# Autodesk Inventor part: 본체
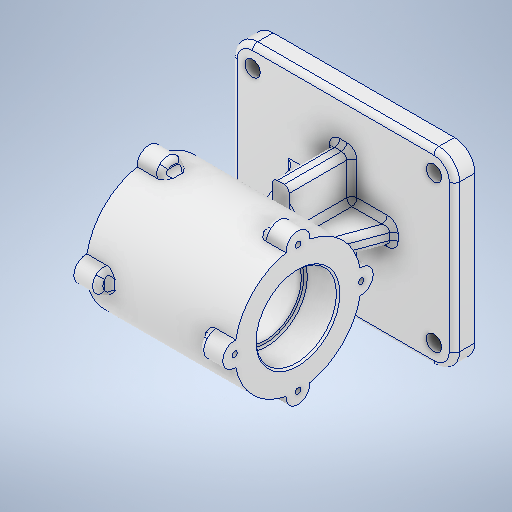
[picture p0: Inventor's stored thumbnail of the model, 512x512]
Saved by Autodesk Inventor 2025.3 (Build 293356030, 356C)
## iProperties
Created: 2025-08
Part Number: 본체
Material: 알루미늄 6061
Document SubType Name: Modeling
Designer: infra011
Density: 2.7 g/cm^3
Appearance: 알루미늄 - 평지
Mass: 1211.2 g
Surface Area: 801.125 cm^2
Volume: 448.594 cm^3
Author: infra011
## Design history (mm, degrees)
sketch "스케치1"
  geometry: L1 (-65, 55)-(65, 55); L2 (65, 55)-(65, -55); L3 (65, -55)-(-65, -55); L4 (-65, -55)-(-65, 55); L5 (-65, 55)-(65, -55); L6 (65, 55)-(-65, -55); 1 further point
  constraints: 12 end point, 2 midpoint, 2 parallel, 1 horizontal, 1 perpendicular
  dimensions: "d0" = 130 distance of L2.end L3.end; "d1" = 110 distance of L1.end L2.end
extrude "돌출1" new body sketch "스케치1" distance "d2" = 12; taper "d3" = 0 deg
sketch "스케치2"
  geometry: L1 (-53, 43)-(53, 43); L2 (53, 43)-(53, -43); L3 (53, -43)-(-53, -43); L4 (-53, -43)-(-53, 43); L5 (-53, 43)-(53, -43); L6 (53, 43)-(-53, -43); 1 further point
  constraints: 12 end point, 2 midpoint, 2 parallel, 1 horizontal, 1 perpendicular
  dimensions: "d4" = 106 distance of L2.end L3.end; "d5" = 86 distance of L1.end L2.end
hole "구멍1" sketch "스케치2" at (-53, 43), (53, -43), (53, 43), (-53, -43) diameter "d6" = 9; stored, may be unused: countersink angle "d10" = 90 deg, drill point angle "d12" = 0 deg; dims "d7" = 8, "d8" = 4, "d9" = 2, "d11" = 12
sketch "스케치3"
  geometry: L1 (43.5, 119)-(-43.5, 119); L2 (-43.5, 119)-(-43.5, 82); L3 (-43.5, 82)-(43.5, 82); L4 (43.5, 82)-(43.5, 119); L5 (43.5, 119)-(-43.5, 82); L6 (-43.5, 119)-(43.5, 82); L7 (65, 0)-(-65, 0) reference; 5 further points
  constraints: 12 end point, 5 midpoint, 2 parallel, 1 horizontal, 1 perpendicular, 1 vertical alignment
  dimensions: "d14" = 37 distance of L1.end L2.end; "d15" = 87 distance of L1.start L1.end; "d16" = 82 distance of point (0, 0) point (0, 82)
revolve "회전1" sketch "스케치3" stored, may be unused: angle "d17" = 90 deg
sketch "스케치4"
  geometry: L1 (43.5, 45)-(43.5, 119) reference; L2 (43.5, 105.5)-(24.5, 105.5); L3 (24.5, 105.5)-(24.5, 82); L4 (24.5, 82)-(43.5, 82); L5 (43.5, 82)-(43.5, 105.5); L6 (24.5, 103)-(-24.5, 103); L7 (-24.5, 103)-(-24.5, 82); L8 (-24.5, 82)-(24.5, 82); L9 (24.5, 82)-(24.5, 103); L10 (-24.5, 105.5)-(-43.5, 105.5); L11 (-43.5, 105.5)-(-43.5, 82); L12 (-43.5, 82)-(-24.5, 82); L13 (-24.5, 82)-(-24.5, 105.5); L14 (-43.5, 45)-(-43.5, 119) reference; L15 (43.5, 45)-(43.5, 119) reference; L16 (-43.5, 45)-(43.5, 45) reference; 4 further points
  constraints: 24 end point, 6 parallel, 3 horizontal, 3 perpendicular, 2 collinear, 2 point on line
  dimensions: "d18" = 19 distance between parallel lines of L5 L9; "d19" = 19 distance between parallel lines of L14 L7; "d20" = 21 distance between parallel lines of L8 L6; "d21" = 23.5 distance between parallel lines of L4 L2; "d22" = 23.5 distance between parallel lines of L12 L10; "d23" = 37 distance between parallel lines of L16 L4; "d24" = 37 distance between parallel lines of L16 L12
revolve "회전2" sketch "스케치4" stored, may be unused: angle "d25" = 90 deg
sketch "스케치5"
  geometry: L1 (0, 0)-(37, 0); C1 r 23.5 at (0, 0) reference; C2 r 7 at (37, 0); C3 r 7 at (0, 37); C4 r 7 at (-37, 0); C5 r 7 at (0, -37); 13 further points
  constraints: 5 coincident, 4 centre point, 2 end point, 1 horizontal, 15 other
  dimensions: "d26" = 14 diameter of C2; "d29" = 360 deg dimension on C1.centre C2.centre (derived)
extrude "돌출2" join sketch "스케치5" distance "d31" = 14; taper "d32" = 0 deg
sketch "스케치6"
  geometry: C1 r 23.5 at (0, 0) reference; C2 r 37 at (0, 0) reference; C3 r 7 at (-37, 0); C4 r 7 at (0, 37); C5 r 7 at (37, 0); C6 r 7 at (0, -37); A1 r 37 centre (0, 0) between (-36.338, 6.969) and (-36.338, -6.969) reference; A2 r 7 centre (-37, 0) between (-36.338, 6.969) and (-36.338, -6.969) reference; A3 r 37 centre (0, 0) between (6.969, 36.338) and (-6.969, 36.338) reference; A4 r 7 centre (0, 37) between (6.969, 36.338) and (-6.969, 36.338) reference; A5 r 37 centre (0, 0) between (36.338, -6.969) and (36.338, 6.969) reference; A6 r 7 centre (37, 0) between (36.338, -6.969) and (36.338, 6.969) reference; A7 r 37 centre (0, 0) between (-6.969, -36.338) and (6.969, -36.338) reference; A8 r 7 centre (0, -37) between (-6.969, -36.338) and (6.969, -36.338) reference; 8 further points
  constraints: 4 centre point, 4 coincident, 1 point on circle
  dimensions: "d33" = 14 diameter of C6; "d34" = 14 diameter of C4; "d35" = 14 diameter of C3; "d36" = 14 diameter of C5
extrude "돌출3" join sketch "스케치6" distance "d37" = 14; taper "d38" = 0 deg
fillet "모깎기1" dims "d39" = 1
chamfer "모따기1" distance "d40" = 1; stored, may be unused: second distance "d41" = 2, angle "d42" = 45 deg
chamfer "모따기2" distance "d43" = 1; stored, may be unused: second distance "d44" = 2, angle "d45" = 45 deg
sketch "스케치7"
  geometry: L1 (43.5, 88.969)-(29.5, 88.969) reference; L2 (29.5, 88.969)-(29.5, 75.031) reference; L3 (29.5, 75.031)-(43.5, 75.031) reference; L4 (43.5, 45.662)-(43.5, 75.031) reference; L5 (43.5, 45.662)-(29.5, 45.662) reference; L6 (29.5, 45.662)-(29.5, 45.662) reference; L7 (29.5, 45.662)-(43.5, 45.662) reference; L8 (43.5, 75.031)-(43.5, 45.662) reference; L9 (43.5, 75.031)-(29.5, 75.031) reference; L10 (29.5, 75.031)-(29.5, 88.969) reference; L11 (29.5, 88.969)-(43.5, 88.969) reference; L12 (43.5, 118.338)-(43.5, 88.969) reference; L13 (43.5, 118.338)-(29.5, 118.338) reference; L14 (29.5, 118.338)-(29.5, 118.338) reference; L15 (29.5, 118.338)-(43.5, 118.338) reference; L16 (43.5, 88.969)-(43.5, 118.338) reference; L17 (-43.5, 45.662)-(-29.5, 45.662) reference; L18 (-29.5, 45.662)-(-29.5, 45.662) reference; L19 (-29.5, 45.662)-(-43.5, 45.662) reference; L20 (-43.5, 45.662)-(-43.5, 75.031) reference; L21 (-43.5, 75.031)-(-29.5, 75.031) reference; L22 (-29.5, 75.031)-(-29.5, 88.969) reference; L23 (-29.5, 88.969)-(-43.5, 88.969) reference; L24 (-43.5, 88.969)-(-43.5, 118.338) reference; L25 (-43.5, 118.338)-(-29.5, 118.338) reference; L26 (-29.5, 118.338)-(-29.5, 118.338) reference; L27 (-29.5, 118.338)-(-43.5, 118.338) reference; L28 (-43.5, 118.338)-(-43.5, 88.969) reference; L29 (-43.5, 88.969)-(-29.5, 88.969) reference; L30 (-29.5, 88.969)-(-29.5, 75.031) reference; L31 (-29.5, 75.031)-(-43.5, 75.031) reference; L32 (-43.5, 75.031)-(-43.5, 45.662) reference; L33 (-29.5, 45)-(29.5, 45) reference; L34 (-65, 0)-(65, 0) reference; L35 (48.5, 12)-(57.5, 12) reference; L36 (-57.5, 12)-(-48.5, 12) reference; L37 (-57.5, 12)-(-48.5, 12) reference; L38 (48.5, 12)-(57.5, 12) reference; L39 (65, 12)-(-65, 12) reference; L40 (-65, 12)-(65, 12) reference; L41 (30, 12)-(17.44, 46.508); L42 (-17.338, 46.787)-(-30, 12); L43 (30, 12)-(-30, 12); L44 (17.44, 46.508)-(-17.338, 46.787); 7 further points
  constraints: 8 end point, 2 midpoint, 2 point on line, 1 collinear, 1 vertical alignment
  dimensions: "d46" = 60 distance of L42.end L41.start; "d47" = 110 deg angle of L39 L41; "d48" = 110 deg angle of L39 L42; "d50" = 30 horizontal distance of point (0, 45) L41.start
extrude "돌출4" join sketch "스케치7" stored distance "d51" = 10; taper "d52" = 0 deg
sketch "스케치9"
  geometry: L1 (-5, -30)-(5, -30); L2 (5, -30)-(5, 30); L3 (5, 30)-(-5, 30); L4 (-5, 30)-(-5, -30); L5 (-65, -55)-(65, -55) reference; 3 further points
  constraints: 8 end point, 2 midpoint, 2 parallel, 1 horizontal, 1 horizontal alignment, 1 perpendicular, 1 vertical alignment
  dimensions: "d59" = 10 distance of L2.end L3.end; "d62" = 60 distance between parallel lines of L3 L1
extrude "돌출6" join sketch "스케치9" distance "d63" = 36.5; taper "d64" = 0 deg
fillet "모깎기2" dims "d65" = 12
fillet "모깎기3" dims "d66" = 3
sketch "스케치10"
  geometry: C1 r 24.5 at (-37, 0) reference; A1 r 37 centre (-37, 0) between (-73.338, -6.969) and (-43.969, -36.338) reference; A2 r 7 centre (-37, -37) between (-43.969, -36.338) and (-30.031, -36.338) reference; A3 r 37 centre (-37, 0) between (-30.031, -36.338) and (-0.662, -6.969) reference; A4 r 7 centre (0, 0) between (-0.662, -6.969) and (-0.662, 6.969) reference; A5 r 37 centre (-37, 0) between (-0.662, 6.969) and (-30.031, 36.338) reference; A6 r 7 centre (-37, 37) between (-30.031, 36.338) and (-43.969, 36.338) reference; A7 r 37 centre (-37, 0) between (-43.969, 36.338) and (-73.338, 6.969) reference; A8 r 7 centre (-74, 0) between (-73.338, 6.969) and (-73.338, -6.969) reference; 1 further point
hole "구멍2" sketch "스케치10" at (-74, 0), (-37, 37), (0, 0), (-37, -37) diameter "d67" = 3.242; stored, may be unused: countersink angle "d71" = 90 deg, drill point angle "d73" = 118 deg; dims "d68" = 8, "d69" = 4, "d70" = 2, "d72" = 10
fillet "모깎기4" dims "d74" = 3
sketch "스케치11"
  geometry: C1 r 24.5 at (37, 0) reference; A1 r 37 centre (37, 0) between (73.338, 6.969) and (43.969, 36.338) reference; A2 r 7 centre (37, 37) between (43.969, 36.338) and (30.031, 36.338) reference; A3 r 37 centre (37, 0) between (30.031, 36.338) and (0.662, 6.969) reference; A4 r 7 centre (0, 0) between (0.662, 6.969) and (0.662, -6.969) reference; A5 r 37 centre (37, 0) between (0.662, -6.969) and (30.031, -36.338) reference; A6 r 7 centre (37, -37) between (30.031, -36.338) and (43.969, -36.338) reference; A7 r 37 centre (37, 0) between (43.969, -36.338) and (73.338, -6.969) reference; A8 r 7 centre (74, 0) between (73.338, -6.969) and (73.338, 6.969) reference; 1 further point
hole "구멍3" sketch "스케치11" at (37, -37), (0, 0), (37, 37), (74, 0) diameter "d75" = 3.242; stored, may be unused: countersink angle "d79" = 90 deg, drill point angle "d81" = 118 deg; dims "d76" = 8, "d77" = 4, "d78" = 2, "d80" = 10
node "솔리드1"
node "투영된 루프1"
node "투영된 루프2"
node "스케치 - 원형 패턴1" dims "d29" = 360 deg (derived)
node "투영된 루프3"
node "투영된 루프4"
node "투영된 루프5"
node "투영된 루프6"
node "투영된 루프7"
node "투영된 루프8"
node "투영된 루프9"
node "투영된 루프10"
feature "A9D066F2-1C7D-4E18-AEED-F7BC21143FA4" dims "d6" = 9, "d7" = 8, "d8" = 4, "d9" = 2, "d10" = 90 deg, "d11" = 12, "d12" = 0
